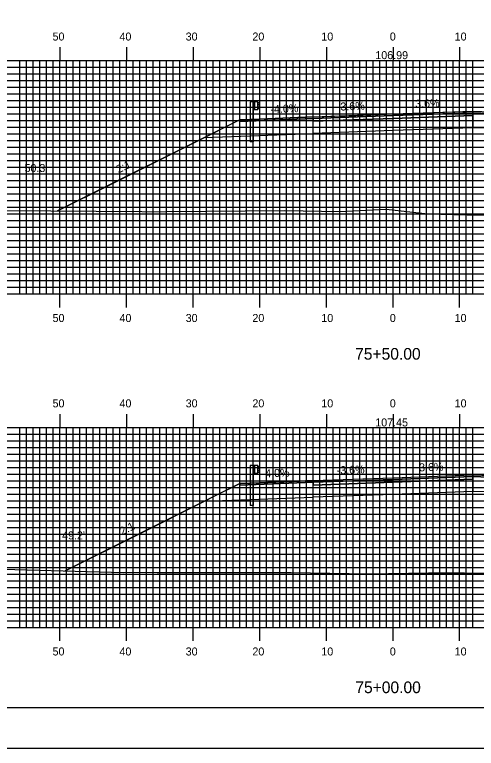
# Model space of a CAD drawing. Extents: x 1761397 to 1761741, y 442591 to 442811.
# Drawn here: x 1761506.5 to 1761575.7, y 442590.5 to 442700.5 of the extents above; entities that cross this region are included whole.
import ezdxf

# ---------------------------------------------------------------- set-up
doc = ezdxf.new("R2010")
doc.units = 0
for name, color, linetype in [('ANNOTATION', 7, 'Continuous'), ('BORDER', 7, 'Continuous'), ('D_Guardrail_Beam_Lt', 7, 'Continuous'), ('D_Roadway_Centerline', 7, 'Continuous'), ('D_Roadway_Centerline_Text', 7, 'Continuous'), ('D_Roadway_Edge_Shoulder', 7, 'Continuous'), ('D_Roadway_Edge_TW', 7, 'Continuous'), ('D_Roadway_Pavement', 7, 'Continuous'), ('D_Roadway_SlopeLines', 7, 'Continuous'), ('D_Roadway_SubGrade', 7, 'Continuous'), ('D_Text_Standard', 7, 'Continuous'), ('H_V ANNOTATION', 7, 'Continuous'), ('MAJOR', 7, 'Continuous'), ('MINOR', 7, 'Continuous'), ('PLOT BOUNDARY', 7, 'Continuous'), ('S_Roadway_Centerline', 7, 'Continuous')]:
    doc.layers.add(name, color=color, linetype=linetype)

msp = doc.modelspace()

# ---------------------------------------------------------------- linework, layer by layer
at = {"layer": 'BORDER'}
msp.add_lwpolyline([(1761413.64, 442596.67), (1761733.64, 442596.67), (1761733.64, 442806.67), (1761413.64, 442806.67)], close=True, dxfattribs=at)
at = {"layer": 'D_Guardrail_Beam_Lt'}
for p, q in [((1761541.81, 442687.49), (1761541.81, 442681.49)), ((1761542.28, 442687.49), (1761541.81, 442687.49)), ((1761542.97, 442687.49), (1761542.28, 442687.49)), ((1761542.28, 442687.49), (1761542.28, 442686.32)), ((1761542.34, 442687.49), (1761542.34, 442686.32)), ((1761542.45, 442687.49), (1761542.45, 442686.32)), ((1761542.97, 442686.32), (1761542.97, 442687.49)), ((1761542.97, 442687.4), (1761543.04, 442687.39)), ((1761543.06, 442687.38), (1761543.2, 442687.28)), ((1761542.28, 442686.32), (1761542.97, 442686.32)), ((1761542.3, 442681.49), (1761542.3, 442686.32)), ((1761542.97, 442686.94), (1761542.97, 442686.87)), ((1761543.04, 442686.42), (1761542.97, 442686.4)), ((1761543.2, 442687.14), (1761543.01, 442687)), ((1761543.01, 442686.8), (1761543.2, 442686.67)), ((1761543.2, 442686.52), (1761543.06, 442686.42)), ((1761542.3, 442681.49), (1761541.81, 442681.49)), ((1761541.81, 442632.95), (1761541.81, 442626.95)), ((1761542.28, 442632.95), (1761541.81, 442632.95)), ((1761542.97, 442632.95), (1761542.28, 442632.95)), ((1761542.28, 442632.95), (1761542.28, 442631.78)), ((1761542.34, 442632.95), (1761542.34, 442631.78)), ((1761542.45, 442632.95), (1761542.45, 442631.78)), ((1761542.97, 442631.78), (1761542.97, 442632.95)), ((1761542.97, 442632.87), (1761543.04, 442632.85)), ((1761542.97, 442632.4), (1761542.97, 442632.33)), ((1761543.2, 442632.6), (1761543.01, 442632.47)), ((1761543.06, 442632.85), (1761543.2, 442632.75)), ((1761542.28, 442631.78), (1761542.97, 442631.78)), ((1761542.3, 442626.95), (1761542.3, 442631.78)), ((1761543.04, 442631.88), (1761542.97, 442631.87)), ((1761543.01, 442632.27), (1761543.2, 442632.13)), ((1761543.2, 442631.99), (1761543.06, 442631.89)), ((1761542.3, 442626.95), (1761541.81, 442626.95))]:
    msp.add_line(p, q, dxfattribs=at)
for centre, major_axis, start_param, end_param in [((1761543.04, 442687.35), (0.0417, 0), 0.959931, 1.376053), ((1761543.05, 442686.94), (-0.0789, 0), 5.323254, 6.283185), ((1761543.05, 442686.87), (-0.0789, 0), 6.283185, 7.243116), ((1761543.04, 442686.46), (0.0417, 0), 4.907132, 5.323254), ((1761543.15, 442687.21), (0.0877, 0), 5.323254, 7.243116), ((1761543.15, 442686.6), (0.0877, 0), 5.323254, 7.243116), ((1761543.05, 442632.4), (-0.0789, 0), 5.323254, 6.283185), ((1761543.05, 442632.33), (-0.0789, 0), 6.283185, 7.243116), ((1761543.04, 442632.81), (0.0417, 0), 0.959931, 1.376053), ((1761543.15, 442632.68), (0.0877, 0), 5.323254, 7.243116), ((1761543.04, 442631.92), (0.0417, 0), 4.907132, 5.323254), ((1761543.15, 442632.06), (0.0877, 0), 5.323254, 7.243116)]:
    msp.add_ellipse(centre, major_axis=major_axis, ratio=0.995501, start_param=start_param, end_param=end_param, dxfattribs=at)
at = {"layer": 'D_Roadway_Centerline'}
for points in [[(1761512.91, 442671.12), (1761512.91, 442671.12), (1761520.88, 442675.1), (1761534.94, 442682.13), (1761534.95, 442682.14), (1761539.62, 442684.47), (1761540.24, 442684.78), (1761543.24, 442684.9), (1761543.24, 442684.9), (1761551.24, 442685.22), (1761557.66, 442685.45), (1761563.24, 442685.66), (1761563.24, 442685.66), (1761574.09, 442686.05), (1761575.24, 442686.09), (1761583.24, 442685.77), (1761586.24, 442685.65), (1761587.33, 442685.1), (1761590.99, 442683.27), (1761591, 442683.27), (1761610.09, 442673.72), (1761617.69, 442669.92), (1761617.7, 442669.92)], [(1761514.07, 442617.16), (1761514.08, 442617.17), (1761525.29, 442622.77), (1761534.85, 442627.55), (1761534.95, 442627.6), (1761534.97, 442627.61), (1761536.43, 442628.35), (1761540.24, 442630.25), (1761540.24, 442630.25), (1761543.24, 442630.37), (1761549.24, 442630.61), (1761551.22, 442630.69), (1761551.24, 442630.69), (1761563.2, 442631.12), (1761563.24, 442631.12), (1761563.28, 442631.12), (1761575.24, 442631.55), (1761583.24, 442631.23), (1761583.24, 442631.23), (1761586.23, 442631.11), (1761586.24, 442631.11), (1761590.73, 442628.87), (1761590.99, 442628.74), (1761615.83, 442616.32)]]:
    msp.add_lwpolyline(points, dxfattribs=at)
at = {"layer": 'D_Roadway_Edge_Shoulder'}
for points in [[(1761551.24, 442685.22), (1761543.24, 442684.9), (1761543.24, 442684.9), (1761540.24, 442684.78), (1761540.24, 442684.53), (1761551.24, 442684.97)], [(1761575.24, 442686.09), (1761583.24, 442685.77), (1761583.24, 442685.77), (1761586.24, 442685.65), (1761586.24, 442685.4), (1761575.24, 442685.84)], [(1761575.24, 442631.55), (1761583.24, 442631.23), (1761583.24, 442631.23), (1761586.24, 442631.11), (1761586.24, 442630.86), (1761575.24, 442631.3)], [(1761551.24, 442630.69), (1761543.24, 442630.37), (1761543.24, 442630.37), (1761540.24, 442630.25), (1761540.24, 442630), (1761551.24, 442630.44)]]:
    msp.add_lwpolyline(points, close=True, dxfattribs=at)
at = {"layer": 'D_Roadway_Edge_TW'}
for points in [[(1761551.24, 442684.97), (1761551.24, 442685.22), (1761563.24, 442685.66), (1761575.24, 442686.09), (1761575.24, 442685.84), (1761563.24, 442685.41)], [(1761551.24, 442630.44), (1761551.24, 442630.69), (1761563.24, 442631.12), (1761575.24, 442631.55), (1761575.24, 442631.3), (1761563.24, 442630.87)]]:
    msp.add_lwpolyline(points, close=True, dxfattribs=at)
at = {"layer": 'D_Roadway_Pavement'}
for points in [[(1761551.24, 442684.56), (1761551.24, 442684.97), (1761563.24, 442685.41), (1761575.24, 442685.84), (1761575.24, 442685.42), (1761563.24, 442684.99)], [(1761551.24, 442630.02), (1761551.24, 442630.44), (1761563.24, 442630.87), (1761575.24, 442631.3), (1761575.24, 442630.89), (1761563.24, 442630.45)]]:
    msp.add_lwpolyline(points, close=True, dxfattribs=at)
for points in [[(1761575.24, 442685.84), (1761575.24, 442685.42)], [(1761551.24, 442684.97), (1761551.24, 442684.56)], [(1761575.24, 442631.3), (1761575.24, 442630.89)], [(1761551.24, 442630.44), (1761551.24, 442630.02)]]:
    msp.add_lwpolyline(points, dxfattribs=at)
at = {"layer": 'D_Roadway_SlopeLines'}
for points in [[(1761540.24, 442684.78), (1761512.91, 442671.12)], [(1761540.24, 442630.25), (1761514.07, 442617.16)]]:
    msp.add_lwpolyline(points, dxfattribs=at)
at = {"layer": 'D_Roadway_SubGrade'}
for points in [[(1761551.24, 442682.72), (1761551.24, 442684.97), (1761551.24, 442684.56), (1761563.24, 442684.99), (1761575.24, 442685.42), (1761575.24, 442685.84), (1761575.24, 442683.59), (1761563.24, 442683.16)], [(1761575.24, 442685.42), (1761575.24, 442685.84), (1761586.24, 442685.4), (1761586.24, 442685.65), (1761590.99, 442683.27), (1761575.24, 442683.59)], [(1761551.24, 442684.56), (1761551.24, 442684.97), (1761540.24, 442684.53), (1761540.24, 442684.78), (1761534.95, 442682.14), (1761551.24, 442682.72)], [(1761551.24, 442628.19), (1761551.24, 442630.44), (1761551.24, 442630.02), (1761563.24, 442630.45), (1761575.24, 442630.89), (1761575.24, 442631.3), (1761575.24, 442629.05), (1761563.24, 442628.62)], [(1761575.24, 442630.89), (1761575.24, 442631.3), (1761586.24, 442630.86), (1761586.24, 442631.11), (1761590.99, 442628.74), (1761575.24, 442629.05)], [(1761551.24, 442630.02), (1761551.24, 442630.44), (1761540.24, 442630), (1761540.24, 442630.25), (1761534.95, 442627.6), (1761551.24, 442628.19)]]:
    msp.add_lwpolyline(points, close=True, dxfattribs=at)
at = {"layer": 'MAJOR'}
for p, q in [((1761513.24, 442695.67), (1761513.24, 442693.67)), ((1761523.24, 442695.67), (1761523.24, 442693.67)), ((1761533.24, 442695.67), (1761533.24, 442693.67)), ((1761543.24, 442695.67), (1761543.24, 442693.67)), ((1761553.24, 442695.67), (1761553.24, 442693.67)), ((1761563.24, 442695.67), (1761563.24, 442693.67)), ((1761573.24, 442695.67), (1761573.24, 442693.67)), ((1761423.24, 442693.67), (1761703.24, 442693.67)), ((1761423.24, 442693.67), (1761703.24, 442693.67)), ((1761513.24, 442658.67), (1761513.24, 442693.67)), ((1761523.24, 442658.67), (1761523.24, 442693.67)), ((1761533.24, 442658.67), (1761533.24, 442693.67)), ((1761543.24, 442658.67), (1761543.24, 442693.67)), ((1761553.24, 442658.67), (1761553.24, 442693.67)), ((1761563.24, 442658.67), (1761563.24, 442693.67)), ((1761573.24, 442658.67), (1761573.24, 442693.67)), ((1761423.24, 442688.67), (1761703.24, 442688.67)), ((1761423.24, 442683.67), (1761703.24, 442683.67)), ((1761423.24, 442678.67), (1761703.24, 442678.67)), ((1761423.24, 442673.67), (1761703.24, 442673.67)), ((1761423.24, 442668.67), (1761703.24, 442668.67)), ((1761423.24, 442663.67), (1761703.24, 442663.67)), ((1761423.24, 442658.67), (1761703.24, 442658.67)), ((1761423.24, 442658.67), (1761703.24, 442658.67)), ((1761513.24, 442656.66), (1761513.24, 442658.67)), ((1761523.24, 442656.66), (1761523.24, 442658.67)), ((1761533.24, 442656.66), (1761533.24, 442658.67)), ((1761543.24, 442656.66), (1761543.24, 442658.67)), ((1761553.24, 442656.66), (1761553.24, 442658.67)), ((1761563.24, 442656.66), (1761563.24, 442658.67)), ((1761573.24, 442656.66), (1761573.24, 442658.67)), ((1761513.24, 442640.67), (1761513.24, 442638.67)), ((1761523.24, 442640.67), (1761523.24, 442638.67)), ((1761533.24, 442640.67), (1761533.24, 442638.67)), ((1761543.24, 442640.67), (1761543.24, 442638.67)), ((1761553.24, 442640.67), (1761553.24, 442638.67)), ((1761563.24, 442640.67), (1761563.24, 442638.67)), ((1761573.24, 442640.67), (1761573.24, 442638.67)), ((1761423.24, 442638.67), (1761703.24, 442638.67)), ((1761423.24, 442638.67), (1761703.24, 442638.67)), ((1761513.24, 442608.67), (1761513.24, 442638.67)), ((1761523.24, 442608.67), (1761523.24, 442638.67)), ((1761533.24, 442608.67), (1761533.24, 442638.67)), ((1761543.24, 442608.67), (1761543.24, 442638.67)), ((1761553.24, 442608.67), (1761553.24, 442638.67)), ((1761563.24, 442608.67), (1761563.24, 442638.67)), ((1761573.24, 442608.67), (1761573.24, 442638.67)), ((1761423.24, 442633.67), (1761703.24, 442633.67)), ((1761423.24, 442628.67), (1761703.24, 442628.67)), ((1761423.24, 442623.67), (1761703.24, 442623.67)), ((1761423.24, 442618.67), (1761703.24, 442618.67)), ((1761423.24, 442613.67), (1761703.24, 442613.67)), ((1761423.24, 442608.67), (1761703.24, 442608.67)), ((1761423.24, 442608.67), (1761703.24, 442608.67)), ((1761513.24, 442606.66), (1761513.24, 442608.67)), ((1761523.24, 442606.66), (1761523.24, 442608.67)), ((1761533.24, 442606.66), (1761533.24, 442608.67)), ((1761543.24, 442606.66), (1761543.24, 442608.67)), ((1761553.24, 442606.66), (1761553.24, 442608.67)), ((1761563.24, 442606.66), (1761563.24, 442608.67)), ((1761573.24, 442606.66), (1761573.24, 442608.67))]:
    msp.add_line(p, q, dxfattribs=at)
at = {"layer": 'MINOR'}
for p, q in [((1761507.24, 442658.67), (1761507.24, 442693.67)), ((1761508.24, 442658.67), (1761508.24, 442693.67)), ((1761509.24, 442658.67), (1761509.24, 442693.67)), ((1761510.24, 442658.67), (1761510.24, 442693.67)), ((1761511.24, 442658.67), (1761511.24, 442693.67)), ((1761512.24, 442658.67), (1761512.24, 442693.67)), ((1761514.24, 442658.67), (1761514.24, 442693.67)), ((1761515.24, 442658.67), (1761515.24, 442693.67)), ((1761516.24, 442658.67), (1761516.24, 442693.67)), ((1761517.24, 442658.67), (1761517.24, 442693.67)), ((1761518.24, 442658.67), (1761518.24, 442693.67)), ((1761519.24, 442658.67), (1761519.24, 442693.67)), ((1761520.24, 442658.67), (1761520.24, 442693.67)), ((1761521.24, 442658.67), (1761521.24, 442693.67)), ((1761522.24, 442658.67), (1761522.24, 442693.67)), ((1761524.24, 442658.67), (1761524.24, 442693.67)), ((1761525.24, 442658.67), (1761525.24, 442693.67)), ((1761526.24, 442658.67), (1761526.24, 442693.67)), ((1761527.24, 442658.67), (1761527.24, 442693.67)), ((1761528.24, 442658.67), (1761528.24, 442693.67)), ((1761529.24, 442658.67), (1761529.24, 442693.67)), ((1761530.24, 442658.67), (1761530.24, 442693.67)), ((1761531.24, 442658.67), (1761531.24, 442693.67)), ((1761532.24, 442658.67), (1761532.24, 442693.67)), ((1761534.24, 442658.67), (1761534.24, 442693.67)), ((1761535.24, 442658.67), (1761535.24, 442693.67)), ((1761536.24, 442658.67), (1761536.24, 442693.67)), ((1761537.24, 442658.67), (1761537.24, 442693.67)), ((1761538.24, 442658.67), (1761538.24, 442693.67)), ((1761539.24, 442658.67), (1761539.24, 442693.67)), ((1761540.24, 442658.67), (1761540.24, 442693.67)), ((1761541.24, 442658.67), (1761541.24, 442693.67)), ((1761542.24, 442658.67), (1761542.24, 442693.67)), ((1761544.24, 442658.67), (1761544.24, 442693.67)), ((1761545.24, 442658.67), (1761545.24, 442693.67)), ((1761546.24, 442658.67), (1761546.24, 442693.67)), ((1761547.24, 442658.67), (1761547.24, 442693.67)), ((1761548.24, 442658.67), (1761548.24, 442693.67)), ((1761549.24, 442658.67), (1761549.24, 442693.67)), ((1761550.24, 442658.67), (1761550.24, 442693.67)), ((1761551.24, 442658.67), (1761551.24, 442693.67)), ((1761552.24, 442658.67), (1761552.24, 442693.67)), ((1761554.24, 442658.67), (1761554.24, 442693.67)), ((1761555.24, 442658.67), (1761555.24, 442693.67)), ((1761556.24, 442658.67), (1761556.24, 442693.67)), ((1761557.24, 442658.67), (1761557.24, 442693.67)), ((1761558.24, 442658.67), (1761558.24, 442693.67)), ((1761559.24, 442658.67), (1761559.24, 442693.67)), ((1761560.24, 442658.67), (1761560.24, 442693.67)), ((1761561.24, 442658.67), (1761561.24, 442693.67)), ((1761562.24, 442658.67), (1761562.24, 442693.67)), ((1761564.24, 442658.67), (1761564.24, 442693.67)), ((1761565.24, 442658.67), (1761565.24, 442693.67)), ((1761566.24, 442658.67), (1761566.24, 442693.67)), ((1761567.24, 442658.67), (1761567.24, 442693.67)), ((1761568.24, 442658.67), (1761568.24, 442693.67)), ((1761569.24, 442658.67), (1761569.24, 442693.67)), ((1761570.24, 442658.67), (1761570.24, 442693.67)), ((1761571.24, 442658.67), (1761571.24, 442693.67)), ((1761572.24, 442658.67), (1761572.24, 442693.67)), ((1761574.24, 442658.67), (1761574.24, 442693.67)), ((1761575.24, 442658.67), (1761575.24, 442693.67)), ((1761423.24, 442692.67), (1761703.24, 442692.67)), ((1761423.24, 442691.67), (1761703.24, 442691.67)), ((1761423.24, 442690.67), (1761703.24, 442690.67)), ((1761423.24, 442689.67), (1761703.24, 442689.67)), ((1761423.24, 442687.67), (1761703.24, 442687.67)), ((1761423.24, 442686.67), (1761703.24, 442686.67)), ((1761423.24, 442685.67), (1761703.24, 442685.67)), ((1761423.24, 442684.67), (1761703.24, 442684.67)), ((1761423.24, 442682.67), (1761703.24, 442682.67)), ((1761423.24, 442681.67), (1761703.24, 442681.67)), ((1761423.24, 442680.67), (1761703.24, 442680.67)), ((1761423.24, 442679.67), (1761703.24, 442679.67)), ((1761423.24, 442677.67), (1761703.24, 442677.67)), ((1761423.24, 442676.67), (1761703.24, 442676.67)), ((1761423.24, 442675.67), (1761703.24, 442675.67)), ((1761423.24, 442674.67), (1761703.24, 442674.67)), ((1761423.24, 442672.67), (1761703.24, 442672.67)), ((1761423.24, 442671.67), (1761703.24, 442671.67)), ((1761423.24, 442670.67), (1761703.24, 442670.67)), ((1761423.24, 442669.67), (1761703.24, 442669.67)), ((1761423.24, 442667.67), (1761703.24, 442667.67)), ((1761423.24, 442666.67), (1761703.24, 442666.67)), ((1761423.24, 442665.67), (1761703.24, 442665.67)), ((1761423.24, 442664.67), (1761703.24, 442664.67)), ((1761423.24, 442662.67), (1761703.24, 442662.67)), ((1761423.24, 442661.67), (1761703.24, 442661.67)), ((1761423.24, 442660.67), (1761703.24, 442660.67)), ((1761423.24, 442659.67), (1761703.24, 442659.67)), ((1761507.24, 442608.67), (1761507.24, 442638.67)), ((1761508.24, 442608.67), (1761508.24, 442638.67)), ((1761509.24, 442608.67), (1761509.24, 442638.67)), ((1761510.24, 442608.67), (1761510.24, 442638.67)), ((1761511.24, 442608.67), (1761511.24, 442638.67)), ((1761512.24, 442608.67), (1761512.24, 442638.67)), ((1761514.24, 442608.67), (1761514.24, 442638.67)), ((1761515.24, 442608.67), (1761515.24, 442638.67)), ((1761516.24, 442608.67), (1761516.24, 442638.67)), ((1761517.24, 442608.67), (1761517.24, 442638.67)), ((1761518.24, 442608.67), (1761518.24, 442638.67)), ((1761519.24, 442608.67), (1761519.24, 442638.67)), ((1761520.24, 442608.67), (1761520.24, 442638.67)), ((1761521.24, 442608.67), (1761521.24, 442638.67)), ((1761522.24, 442608.67), (1761522.24, 442638.67)), ((1761524.24, 442608.67), (1761524.24, 442638.67)), ((1761525.24, 442608.67), (1761525.24, 442638.67)), ((1761526.24, 442608.67), (1761526.24, 442638.67)), ((1761527.24, 442608.67), (1761527.24, 442638.67)), ((1761528.24, 442608.67), (1761528.24, 442638.67)), ((1761529.24, 442608.67), (1761529.24, 442638.67)), ((1761530.24, 442608.67), (1761530.24, 442638.67)), ((1761531.24, 442608.67), (1761531.24, 442638.67)), ((1761532.24, 442608.67), (1761532.24, 442638.67)), ((1761534.24, 442608.67), (1761534.24, 442638.67)), ((1761535.24, 442608.67), (1761535.24, 442638.67)), ((1761536.24, 442608.67), (1761536.24, 442638.67)), ((1761537.24, 442608.67), (1761537.24, 442638.67)), ((1761538.24, 442608.67), (1761538.24, 442638.67)), ((1761539.24, 442608.67), (1761539.24, 442638.67)), ((1761540.24, 442608.67), (1761540.24, 442638.67)), ((1761541.24, 442608.67), (1761541.24, 442638.67)), ((1761542.24, 442608.67), (1761542.24, 442638.67)), ((1761544.24, 442608.67), (1761544.24, 442638.67)), ((1761545.24, 442608.67), (1761545.24, 442638.67)), ((1761546.24, 442608.67), (1761546.24, 442638.67)), ((1761547.24, 442608.67), (1761547.24, 442638.67)), ((1761548.24, 442608.67), (1761548.24, 442638.67)), ((1761549.24, 442608.67), (1761549.24, 442638.67)), ((1761550.24, 442608.67), (1761550.24, 442638.67)), ((1761551.24, 442608.67), (1761551.24, 442638.67)), ((1761552.24, 442608.67), (1761552.24, 442638.67)), ((1761554.24, 442608.67), (1761554.24, 442638.67)), ((1761555.24, 442608.67), (1761555.24, 442638.67)), ((1761556.24, 442608.67), (1761556.24, 442638.67)), ((1761557.24, 442608.67), (1761557.24, 442638.67)), ((1761558.24, 442608.67), (1761558.24, 442638.67)), ((1761559.24, 442608.67), (1761559.24, 442638.67)), ((1761560.24, 442608.67), (1761560.24, 442638.67)), ((1761561.24, 442608.67), (1761561.24, 442638.67)), ((1761562.24, 442608.67), (1761562.24, 442638.67)), ((1761564.24, 442608.67), (1761564.24, 442638.67)), ((1761565.24, 442608.67), (1761565.24, 442638.67)), ((1761566.24, 442608.67), (1761566.24, 442638.67)), ((1761567.24, 442608.67), (1761567.24, 442638.67)), ((1761568.24, 442608.67), (1761568.24, 442638.67)), ((1761569.24, 442608.67), (1761569.24, 442638.67)), ((1761570.24, 442608.67), (1761570.24, 442638.67)), ((1761571.24, 442608.67), (1761571.24, 442638.67)), ((1761572.24, 442608.67), (1761572.24, 442638.67)), ((1761574.24, 442608.67), (1761574.24, 442638.67)), ((1761575.24, 442608.67), (1761575.24, 442638.67)), ((1761423.24, 442637.67), (1761703.24, 442637.67)), ((1761423.24, 442636.67), (1761703.24, 442636.67)), ((1761423.24, 442635.67), (1761703.24, 442635.67)), ((1761423.24, 442634.67), (1761703.24, 442634.67)), ((1761423.24, 442632.67), (1761703.24, 442632.67)), ((1761423.24, 442631.67), (1761703.24, 442631.67)), ((1761423.24, 442630.67), (1761703.24, 442630.67)), ((1761423.24, 442629.67), (1761703.24, 442629.67)), ((1761423.24, 442627.67), (1761703.24, 442627.67)), ((1761423.24, 442626.67), (1761703.24, 442626.67)), ((1761423.24, 442625.67), (1761703.24, 442625.67)), ((1761423.24, 442624.67), (1761703.24, 442624.67)), ((1761423.24, 442622.67), (1761703.24, 442622.67)), ((1761423.24, 442621.67), (1761703.24, 442621.67)), ((1761423.24, 442620.67), (1761703.24, 442620.67)), ((1761423.24, 442619.67), (1761703.24, 442619.67)), ((1761423.24, 442617.67), (1761703.24, 442617.67)), ((1761423.24, 442616.67), (1761703.24, 442616.67)), ((1761423.24, 442615.67), (1761703.24, 442615.67)), ((1761423.24, 442614.67), (1761703.24, 442614.67)), ((1761423.24, 442612.67), (1761703.24, 442612.67)), ((1761423.24, 442611.67), (1761703.24, 442611.67)), ((1761423.24, 442610.67), (1761703.24, 442610.67)), ((1761423.24, 442609.67), (1761703.24, 442609.67))]:
    msp.add_line(p, q, dxfattribs=at)
at = {"layer": 'PLOT BOUNDARY'}
msp.add_lwpolyline([(1761397.45, 442590.55), (1761737.45, 442590.55), (1761737.45, 442810.55), (1761397.45, 442810.55)], close=True, dxfattribs=at)
at = {"layer": 'S_Roadway_Centerline'}
for points in [[(1761505.08, 442671.17), (1761525.57, 442671.03), (1761527.25, 442671), (1761529.25, 442671.06), (1761546.94, 442671.2), (1761555.31, 442671.06), (1761562.19, 442671.37), (1761568.45, 442670.7), (1761574.37, 442670.52), (1761581.2, 442670.52), (1761590.04, 442670.49), (1761606.12, 442670.18), (1761611.91, 442670.09), (1761621.05, 442669.82), (1761632.88, 442669.81)], [(1761502.88, 442617.47), (1761522.82, 442616.92), (1761525.19, 442616.95), (1761527.85, 442616.93), (1761540.5, 442616.92), (1761546.09, 442616.92), (1761546.91, 442616.91), (1761547.95, 442616.91), (1761559.54, 442616.7), (1761568.56, 442616.84), (1761573.96, 442616.85), (1761589.96, 442616.74), (1761593.35, 442616.73), (1761597.6, 442616.54), (1761605.31, 442616.22), (1761612.37, 442616.27), (1761617.39, 442616.34), (1761622.81, 442616.06)]]:
    msp.add_lwpolyline(points, dxfattribs=at)

# ---------------------------------------------------------------- texts
at = {"layer": 'ANNOTATION'}
for s, rotation, p in [('-3.6%', 2.0618, (1761554.83, 442686.15)), ('3.6%', 2.0617, (1761566.58, 442686.58)), ('-4.0%', 2.2906, (1761544.87, 442685.77)), ('2:1', 26.5646, (1761522.07, 442676.73)), ('-4.0%', 2.2907, (1761543.56, 442631.14)), ('-3.6%', 2.0616, (1761554.81, 442631.62)), ('3.6%', 2.0618, (1761567.17, 442632.06)), ('2:1', 26.5668, (1761522.61, 442622.47))]:
    msp.add_text(s, height=1.2, rotation=rotation, dxfattribs=at).set_placement(p)
at = {"layer": 'D_Roadway_Centerline'}
for s, p in [('C', (1761563.23, 442685.66)), ('L', (1761563.24, 442685.65)), ('C', (1761563.24, 442631.12)), ('L', (1761563.24, 442631.11))]:
    msp.add_text(s, height=0.0146, dxfattribs=at).set_placement(p)
at = {"layer": 'D_Roadway_Centerline_Text'}
for s, p in [('106.99', (1761560.59, 442693.88)), ('107.45', (1761560.58, 442638.81))]:
    msp.add_text(s, height=1.2, dxfattribs=at).set_placement(p)
at = {"layer": 'D_Text_Standard'}
for s, p in [("50.3'", (1761507.96, 442676.95)), ("49.2'", (1761513.6, 442621.87))]:
    msp.add_text(s, height=1.2, dxfattribs=at).set_placement(p)
at = {"layer": 'H_V ANNOTATION'}
for s, height, p in [('50', 1.2, (1761512.17, 442696.67)), ('40', 1.2, (1761522.21, 442696.67)), ('30', 1.2, (1761532.14, 442696.67)), ('20', 1.2, (1761542.15, 442696.67)), ('10', 1.2, (1761552.49, 442696.67)), ('0', 1.2, (1761562.76, 442696.67)), ('10', 1.2, (1761572.49, 442696.67)), ('50', 1.2, (1761512.17, 442654.47)), ('40', 1.2, (1761522.21, 442654.47)), ('30', 1.2, (1761532.14, 442654.47)), ('20', 1.2, (1761542.15, 442654.47)), ('10', 1.2, (1761552.49, 442654.47)), ('0', 1.2, (1761562.76, 442654.47)), ('10', 1.2, (1761572.49, 442654.47)), ('75+50.00', 1.75, (1761557.56, 442648.82)), ('50', 1.2, (1761512.17, 442641.67)), ('40', 1.2, (1761522.21, 442641.67)), ('30', 1.2, (1761532.14, 442641.67)), ('20', 1.2, (1761542.15, 442641.67)), ('10', 1.2, (1761552.49, 442641.67)), ('0', 1.2, (1761562.76, 442641.67)), ('10', 1.2, (1761572.49, 442641.67)), ('50', 1.2, (1761512.17, 442604.47)), ('40', 1.2, (1761522.21, 442604.47)), ('30', 1.2, (1761532.14, 442604.47)), ('20', 1.2, (1761542.15, 442604.47)), ('10', 1.2, (1761552.49, 442604.47)), ('0', 1.2, (1761562.76, 442604.47)), ('10', 1.2, (1761572.49, 442604.47)), ('75+00.00', 1.75, (1761557.59, 442598.82))]:
    msp.add_text(s, height=height, dxfattribs=at).set_placement(p)

doc.saveas('drawing.dxf')
